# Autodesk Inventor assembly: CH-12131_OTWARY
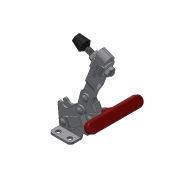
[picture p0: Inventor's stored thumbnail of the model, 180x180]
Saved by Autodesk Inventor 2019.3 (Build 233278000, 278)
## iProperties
Company: Î¢ÈíÖÐ¹ú
Created: 2012-09
Part Number: CH-12131_OTWARY
Material: Ogólny
Description: STEP AP203
Document SubType Name: Assembly
Designer: CADENGINEERING4
Sending System: SolidWorks 2010
Preprocessor: SwSTEP 2.0
Title: CH-12131.STEP
Author: Î¢ÈíÓÃ»§
Revision Number: ÈÎºÎ
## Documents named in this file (11)
- D:\Vault_2016\Projekty\NASZ KATALOG\CLAMPTEK\STRONA\Vertical toggle clamp\CH-12131\CH-12131_OTWARY.iam
- D:\Vault_2016\Projekty\NASZ KATALOG\CLAMPTEK\STEP FILES\Vertical toggle clamp\CH-12131\CH-FW-516.ipt
- D:\Vault_2016\Projekty\NASZ KATALOG\CLAMPTEK\STEP FILES\Vertical toggle clamp\CH-12131\CH-FC-56212 Nut.ipt
- D:\Vault_2016\Projekty\NASZ KATALOG\CLAMPTEK\STEP FILES\Vertical toggle clamp\CH-12131\CH-12130-06.ipt
- D:\Vault_2016\Projekty\NASZ KATALOG\CLAMPTEK\STEP FILES\Vertical toggle clamp\CH-12131\CH-12148-03 T-HANDLE.ipt
- D:\Vault_2016\Projekty\NASZ KATALOG\CLAMPTEK\STEP FILES\Vertical toggle clamp\CH-12131\CH-FC-56212 SPINDLE SUPPLIED.ipt
- D:\Vault_2016\Projekty\NASZ KATALOG\CLAMPTEK\STEP FILES\Vertical toggle clamp\CH-12131\CH-12130-01 FLANGED BASE.ipt
- D:\Vault_2016\Projekty\NASZ KATALOG\CLAMPTEK\STEP FILES\Vertical toggle clamp\CH-12131\CH-12130-04 CONNECTING-PLATE.ipt
- D:\Vault_2016\Projekty\NASZ KATALOG\CLAMPTEK\STEP FILES\Vertical toggle clamp\CH-12131\CH-12131-02 SHORT U-BAR.ipt
- D:\Vault_2016\Projekty\NASZ KATALOG\CLAMPTEK\STEP FILES\Vertical toggle clamp\CH-12131\CH-12130-08.ipt
- D:\Vault_2016\Projekty\NASZ KATALOG\CLAMPTEK\STEP FILES\Vertical toggle clamp\CH-12131\CH-12130-05.ipt
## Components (14 placed, 10 different names)
1. CH-12130-01 FLANGED BASE_9
2. CH-FW-516:3 — Zestawiające:19, Zestawiające:23, Zestawiające:25, Równoległe:1, Równoległe:2, Kątowe:1
3. CH-FC-56212 Nut:3 — Zestawiające:20, Zestawiające:21, Zestawiające:24, Zestawiające:26, Zestawiające:27
4. CH-12130-06:3 — Zestawiające:16, Zestawiające:17
5. CH-12130-06:4 — Zestawiające:5, Zestawiające:6, Zestawiające:7, Zestawiające:8
6. CH-12148-03 T-HANDLE:2 — Zestawiające:2, Zestawiające:3, Zestawiające:4, Zestawiające:11, Zestawiające:12, Zestawiające:14, Zestawiające:15
7. CH-FC-56212 Nut:4 — Zestawiające:18, Zestawiające:19, Zestawiające:20, Zestawiające:25
8. CH-FC-56212 SPINDLE SUPPLIED:2 — Zestawiające:18, Równoległe:3
9. CH-FW-516:4 — Zestawiające:21, Zestawiające:22, Zestawiające:24, Równoległe:1, Równoległe:2
10. CH-12130-04 CONNECTING-PLATE:2 — Zestawiające:5, Zestawiające:7, Zestawiające:8, Zestawiające:9, Zestawiające:10, Zestawiające:13, Zestawiające:15, Zestawiające:17
11. CH-12131-02 SHORT U-BAR:2 — Zestawiające:6, Zestawiające:9, Zestawiające:16, Zestawiające:22, Zestawiające:23, Zestawiające:26, Zestawiające:27, Kątowe:1, Równoległe:3
12. CH-12130-08:3 — Zestawiające:10, Zestawiające:11, Zestawiające:12, Zestawiające:13, Zestawiające:14
13. CH-12130-08:4 — Zestawiające:1, Zestawiające:2, Zestawiające:3, Zestawiające:4
14. CH-12130-05:2 — Zestawiające:1
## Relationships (31: Mate 27, Flush 3, Angle 1)
- Zestawiające:1 [Mate]: CH-12130-08:4 ↔ CH-12130-05:2
- Zestawiające:2 [Mate]: CH-12148-03 T-HANDLE:2 ↔ CH-12130-08:4
- Zestawiające:3 [Mate]: CH-12148-03 T-HANDLE:2 ↔ CH-12130-08:4
- Zestawiające:4 [Mate]: CH-12148-03 T-HANDLE:2 ↔ CH-12130-08:4
- Zestawiające:5 [Mate]: CH-12130-06:4 ↔ CH-12130-04 CONNECTING-PLATE:2
- Zestawiające:6 [Mate]: CH-12130-06:4 ↔ CH-12131-02 SHORT U-BAR:2
- Zestawiające:7 [Mate]: CH-12130-06:4 ↔ CH-12130-04 CONNECTING-PLATE:2
- Zestawiające:8 [Mate]: CH-12130-06:4 ↔ CH-12130-04 CONNECTING-PLATE:2
- Zestawiające:9 [Mate]: CH-12130-04 CONNECTING-PLATE:2 ↔ CH-12131-02 SHORT U-BAR:2
- Zestawiające:10 [Mate]: CH-12130-04 CONNECTING-PLATE:2 ↔ CH-12130-08:3
- Zestawiające:11 [Mate]: CH-12148-03 T-HANDLE:2 ↔ CH-12130-08:3
- Zestawiające:12 [Mate]: CH-12148-03 T-HANDLE:2 ↔ CH-12130-08:3
- Zestawiające:13 [Mate]: CH-12130-04 CONNECTING-PLATE:2 ↔ CH-12130-08:3
- Zestawiające:14 [Mate]: CH-12148-03 T-HANDLE:2 ↔ CH-12130-08:3
- Zestawiające:15 [Mate]: CH-12148-03 T-HANDLE:2 ↔ CH-12130-04 CONNECTING-PLATE:2
- Zestawiające:16 [Mate]: CH-12130-06:3 ↔ CH-12131-02 SHORT U-BAR:2
- Zestawiające:17 [Mate]: CH-12130-06:3 ↔ CH-12130-04 CONNECTING-PLATE:2
- Zestawiające:18 [Mate]: CH-FC-56212 Nut:4 ↔ CH-FC-56212 SPINDLE SUPPLIED:2
- Zestawiające:19 [Mate]: CH-FW-516:3 ↔ CH-FC-56212 Nut:4
- Zestawiające:20 [Mate]: CH-FC-56212 Nut:3 ↔ CH-FC-56212 Nut:4
- Zestawiające:21 [Mate]: CH-FC-56212 Nut:3 ↔ CH-FW-516:4
- Zestawiające:22 [Mate]: CH-FW-516:4 ↔ CH-12131-02 SHORT U-BAR:2
- Zestawiające:23 [Mate]: CH-FW-516:3 ↔ CH-12131-02 SHORT U-BAR:2
- Zestawiające:24 [Mate]: CH-FC-56212 Nut:3 ↔ CH-FW-516:4
- Zestawiające:25 [Mate]: CH-FW-516:3 ↔ CH-FC-56212 Nut:4
- Równoległe:1 [Flush]: CH-FW-516:3 ↔ CH-FW-516:4
- Zestawiające:26 [Mate]: CH-FC-56212 Nut:3 ↔ CH-12131-02 SHORT U-BAR:2
- Zestawiające:27 [Mate]: CH-FC-56212 Nut:3 ↔ CH-12131-02 SHORT U-BAR:2
- Równoległe:2 [Flush]: CH-FW-516:3 ↔ CH-FW-516:4
- Kątowe:1 [Angle]: CH-FW-516:3 ↔ CH-12131-02 SHORT U-BAR:2
- Równoległe:3 [Flush]: CH-FC-56212 SPINDLE SUPPLIED:2 ↔ CH-12131-02 SHORT U-BAR:2
